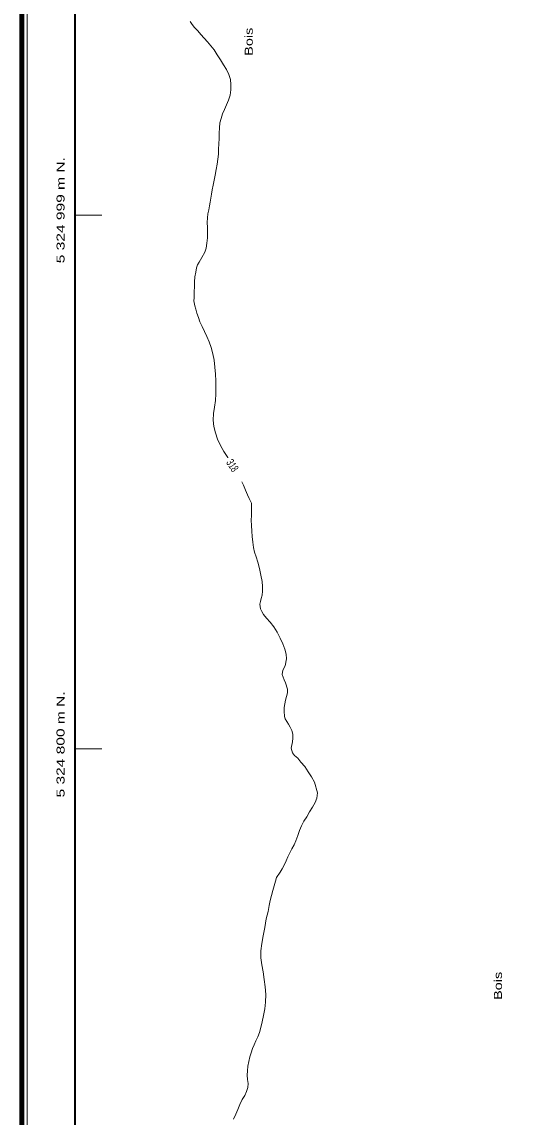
# Model space of a CAD drawing. Extents: x 240591 to 242335, y 5323482 to 5326937.
# Drawn here: x 240590.8 to 240776.2, y 5324661.9 to 5325072.5 of the extents above; entities that cross this region are included whole.
import ezdxf
from ezdxf.enums import TextEntityAlignment as Align

# ---------------------------------------------------------------- set-up
doc = ezdxf.new("R2010")
doc.units = 0
doc.header["$LTSCALE"] = 1.2
doc.linetypes.add('LONG_DASHED', pattern=[7.5, 6, -1.5])
for name, color, linetype, lineweight in [('2', 7, 'Continuous', 13), ('44', 7, 'Continuous', 25), ('60', 7, 'Continuous', 35), ('61', 7, 'Continuous', 13)]:
    doc.layers.add(name, color=color, linetype=linetype, lineweight=lineweight)

msp = doc.modelspace()

# ---------------------------------------------------------------- linework, layer by layer
at = {"layer": '2', "linetype": 'LONG_DASHED'}
for points in [[(240660.2, 5324954.5), (240658.4, 5324958.3), (240657.6, 5324960), (240657, 5324961.7), (240656.4, 5324963.3), (240656, 5324964.8), (240655.7, 5324966), (240655.3, 5324967.9), (240655.4, 5324969), (240655.4, 5324971.5), (240655.5, 5324973.1), (240655.6, 5324975), (240655.7, 5324976.9), (240656, 5324978.7), (240656.3, 5324980.3), (240656.7, 5324981.4), (240657.3, 5324982.4), (240658.3, 5324984.2), (240659.4, 5324986.2), (240659.9, 5324987.7), (240660.2, 5324989.6), (240660.4, 5324991.5), (240660.4, 5324993.5), (240660.4, 5324995.4), (240660.3, 5324997.3), (240660.4, 5324999), (240660.6, 5325000.6), (240660.9, 5325002.1), (240661.2, 5325003.5), (240661.4, 5325004.9), (240661.7, 5325006.4), (240661.9, 5325007.9), (240662.2, 5325009.6), (240662.5, 5325011.3), (240662.9, 5325013.2), (240663.3, 5325015.1), (240663.7, 5325017.1), (240664, 5325019.1), (240664.3, 5325021), (240664.5, 5325022.9), (240664.6, 5325024.8), (240664.7, 5325026.8), (240664.8, 5325028.8), (240664.8, 5325030.8), (240664.9, 5325032.8), (240665.1, 5325034.6), (240665.5, 5325036.3), (240666.1, 5325038), (240666.8, 5325039.7), (240667.6, 5325041.4), (240668.3, 5325043.1), (240668.9, 5325045), (240669.2, 5325047), (240669.2, 5325049), (240669, 5325050.9), (240668.4, 5325052.8), (240667.5, 5325054.6), (240666.4, 5325056.4), (240665.3, 5325058.3), (240664.1, 5325060.2), (240662.9, 5325062), (240661.7, 5325063.5), (240660.4, 5325065), (240659.2, 5325066.4), (240657.9, 5325067.8), (240656.8, 5325069.1), (240655.6, 5325070.4), (240654.7, 5325071.5), (240653.9, 5325072.7)], [(240668.1, 5324909), (240668, 5324909.2), (240666.6, 5324911.4), (240665.3, 5324913.7), (240664.2, 5324916), (240663.4, 5324918.4), (240662.8, 5324920.8), (240662.6, 5324923.2), (240662.7, 5324925.7), (240663.1, 5324928.1), (240663.4, 5324930.6), (240663.6, 5324933), (240663.6, 5324935.4), (240663.5, 5324937.9), (240663.4, 5324940.4), (240663.2, 5324943.1), (240662.9, 5324945.7), (240662.4, 5324948.1), (240661.8, 5324950.4), (240661, 5324952.5), (240660.2, 5324954.5)], [(240701.7, 5324783.4), (240700.6, 5324787.4), (240699.5, 5324789.4), (240698.2, 5324791.3), (240696.9, 5324793.3), (240695.5, 5324795), (240694.3, 5324796.4), (240693.1, 5324797.5), (240692.3, 5324798.4), (240691.8, 5324800.2), (240692.3, 5324802.6), (240692.5, 5324804), (240692.4, 5324805.4), (240692.1, 5324806.8), (240691.4, 5324808.1), (240690.8, 5324809.2), (240689.6, 5324811.2), (240689.3, 5324812.1), (240689.2, 5324814.1), (240689.2, 5324815.4), (240689.4, 5324816.8), (240689.7, 5324818.2), (240690.1, 5324819.6), (240690.4, 5324821), (240690.5, 5324822.3), (240689.7, 5324824.7), (240689.2, 5324825.8), (240688.4, 5324827.8), (240688.7, 5324829.4), (240689.6, 5324831.1), (240690.1, 5324833.7), (240689.9, 5324835.4), (240689.4, 5324837.3), (240688.7, 5324839.3), (240687.7, 5324841.4), (240686.6, 5324843.7), (240685.3, 5324845.7), (240683.9, 5324847.4), (240682.6, 5324848.9), (240681.5, 5324850.3), (240680.8, 5324851.4), (240680.3, 5324852.4), (240680.1, 5324854.2), (240680.3, 5324855.2), (240680.6, 5324856.3), (240680.9, 5324857.6), (240681.1, 5324859.1), (240681.1, 5324860.8), (240680.9, 5324862.7), (240680.5, 5324865), (240679.9, 5324867.5), (240679.3, 5324869.9), (240678.7, 5324871.9), (240678.1, 5324873.7), (240677.7, 5324875.4), (240677.5, 5324877.4), (240677.2, 5324879.5), (240677.1, 5324881.5), (240676.9, 5324883.7), (240676.8, 5324885.7), (240676.9, 5324887.4), (240676.9, 5324888.8), (240677, 5324890.7), (240677, 5324891.5), (240676.9, 5324892), (240676.1, 5324893.8), (240675.5, 5324895.2), (240674.7, 5324896.9), (240673.9, 5324898.8), (240673.3, 5324900)], [(240670.2, 5324661.1), (240671, 5324662.9), (240671.8, 5324664.7), (240672.6, 5324666.6), (240673.5, 5324668.4), (240674.4, 5324670), (240675.1, 5324671.4), (240675.6, 5324672.9), (240675.7, 5324674.4), (240675.5, 5324676), (240675.3, 5324677.6), (240675.4, 5324679.2), (240675.6, 5324680.9), (240675.9, 5324682.7), (240676.3, 5324684.4), (240676.8, 5324686), (240677.3, 5324687.6), (240677.9, 5324689), (240678.6, 5324690.4), (240679.3, 5324692), (240679.9, 5324693.6), (240680.5, 5324695.5), (240681, 5324697.6), (240681.5, 5324699.9), (240681.9, 5324702.4), (240682.2, 5324705), (240682.3, 5324707.8), (240682.1, 5324710.7), (240681.7, 5324713.5), (240681.3, 5324716.3), (240680.8, 5324719), (240680.5, 5324721.6), (240680.5, 5324724.2), (240680.8, 5324726.9), (240681.3, 5324729.8), (240681.9, 5324733), (240682.5, 5324736.2), (240683.2, 5324739), (240683.6, 5324741.2), (240684, 5324743.1), (240684.5, 5324744.9), (240684.9, 5324746.8), (240685.4, 5324748.6), (240685.9, 5324750.3), (240686.3, 5324751.7), (240687.7, 5324753.7), (240688.5, 5324754.9), (240689.2, 5324756.3), (240689.9, 5324757.9), (240690.6, 5324759.4), (240691.3, 5324760.9), (240692.1, 5324762.4), (240692.9, 5324763.9), (240693.6, 5324765.5), (240694.3, 5324767.4), (240694.9, 5324769.3), (240695.7, 5324771.1), (240696.6, 5324772.8), (240697.7, 5324774.5), (240698.7, 5324776.3), (240699.8, 5324778.1), (240700.8, 5324779.8), (240701.5, 5324781.5), (240701.7, 5324783.4)]]:
    msp.add_lwpolyline(points, dxfattribs=at)
at = {"layer": '60', "lineweight": 158}
msp.add_lwpolyline([(242321.7, 5323482.5), (240590.8, 5323482.5), (240590.8, 5326907.9), (242321.7, 5326907.9)], close=True, dxfattribs=at)
at = {"layer": '60', "lineweight": 13}
msp.add_lwpolyline([(240592.8, 5323484.5), (240592.8, 5326905.9), (242319.7, 5326905.9), (242319.7, 5323484.5)], close=True, dxfattribs=at)
at = {"layer": '60'}
msp.add_lwpolyline([(240610.8, 5326369.9), (242301.7, 5326369.9), (242301.7, 5323502.5), (240610.8, 5323502.5)], close=True, dxfattribs=at)
at = {"layer": '61'}
for p, q in [((240610.8, 5325000), (240620.8, 5325000)), ((240610.8, 5324800), (240620.8, 5324800))]:
    msp.add_line(p, q, dxfattribs=at)

# ---------------------------------------------------------------- texts
at = {"layer": '2', "width": 0.6}
msp.add_text('318', height=3, rotation=303.329, dxfattribs=at).set_placement((240667.3, 5324907.3))
at = {"layer": '44', "width": 1.35}
for p in [(240677.4, 5325059.8), (240770.9, 5324705.8)]:
    msp.add_text('Bois', height=3, rotation=90, dxfattribs=at).set_placement(p)
at = {"layer": '61', "width": 1.45}
for s, p in [('5 324 999 m N.', (240606.8, 5325001.9)), ('5 324 800 m N.', (240606.8, 5324801.6))]:
    msp.add_text(s, height=3, rotation=90, dxfattribs=at).set_placement(p, align=Align.CENTER)

doc.saveas('drawing.dxf')
